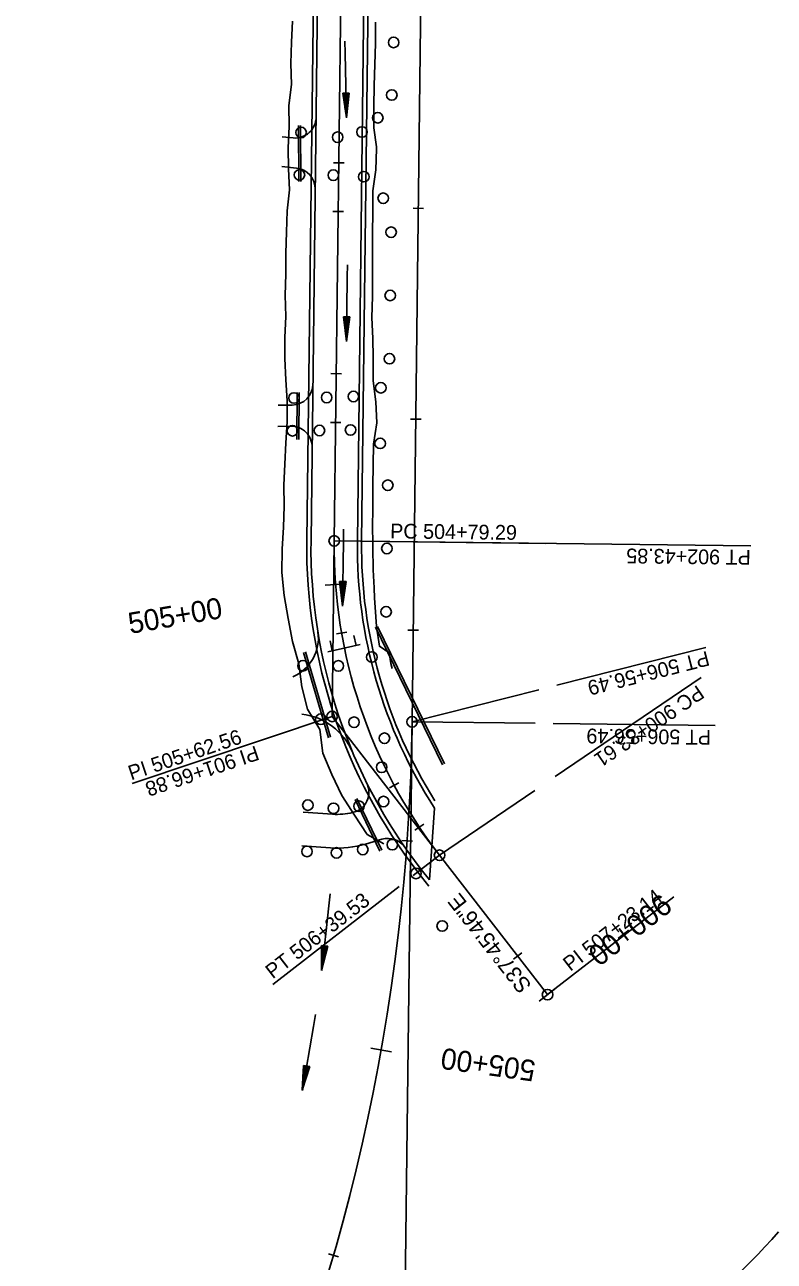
# Model space of a CAD drawing. Extents: x 1300404 to 1323571, y 234004 to 252077.
# Drawn here: x 1309789 to 1310144, y 240637 to 241223 of the extents above; entities that cross this region are included whole.
import ezdxf

# ---------------------------------------------------------------- set-up
doc = ezdxf.new("R2010")
doc.units = 0
for name, color, linetype in [('R_Barrel', 7, 'Continuous'), ('R_Const Limits', 7, 'Continuous'), ('R_Detour', 7, 'Continuous'), ('R_Flow Arrows', 7, 'Continuous'), ('R_Horz Alg Annot', 7, 'Continuous'), ('R_Horz Alg Annot Leader', 7, 'Continuous'), ('R_Horz Alg Major Ticks', 7, 'Continuous'), ('R_Horz Alg Minor Ticks', 7, 'Continuous'), ('R_Horz Alg Station Annot', 7, 'Continuous'), ('R_Horz Alg Tangents', 7, 'Continuous'), ('R_Lane Edge', 7, 'Continuous'), ('R_MOT Proposed', 7, 'Continuous'), ('R_No Plot', 7, 'Continuous'), ('R_Proposed', 7, 'Continuous'), ('R_Shoulder', 7, 'Continuous'), ('R_Temp Drainage', 7, 'Continuous')]:
    doc.layers.add(name, color=color, linetype=linetype)

msp = doc.modelspace()

# ---------------------------------------------------------------- linework, layer by layer
at = {"layer": 'R_Barrel'}
for p, q in [((1309945.82, 240929.07), (1309944.77, 240933.75)), ((1309947.77, 240929.51), (1309932.32, 240926.06)), ((1309934.43, 240926.53), (1309933.39, 240931.2))]:
    msp.add_line(p, q, dxfattribs=at)
for centre in [(1309963.56, 241215.04), (1309962.67, 241190.12), (1309956.03, 241179.33), (1309919.68, 241172.34), (1309937, 241170.1), (1309948.56, 241172.58), (1309918.9, 241152.22), (1309934.97, 241152.09), (1309949.43, 241151.36), (1309958.65, 241141.16), (1309962.37, 241125.05), (1309961.97, 241095.05), (1309961.57, 241065.05), (1309944.5, 241047.14), (1309957.49, 241051.27), (1309916.32, 241046.44), (1309931.8, 241046.67), (1309915.58, 241030.89), (1309928.37, 241031.02), (1309943.16, 241031.28), (1309957.19, 241024.9), (1309960.78, 241005.06), (1309960.38, 240975.06), (1309959.99, 240945.06), (1309920.57, 240919.45), (1309937.35, 240919.38), (1309953.23, 240923.58), (1309929.03, 240894.12), (1309944.8, 240892.66), (1309959.19, 240885.07), (1309957.9, 240871.31), (1309922.89, 240853.37), (1309958.79, 240855.07), (1309935.04, 240851.85), (1309947.15, 240852.84), (1309922.48, 240831.42), (1309936.48, 240830.72), (1309948.95, 240832.32), (1309962.94, 240834.63), (1309974.17, 240820.96), (1309986.63, 240796.05)]:
    msp.add_circle(centre, 2.5, dxfattribs=at)
at = {"layer": 'R_Const Limits'}
for points in [[(1310136.46, 240640.42), (1310136.46, 240640.42), (1310139.66, 240643.87), (1310142.9, 240647.43), (1310146.08, 240651.04)], [(1310032.23, 240538.98), (1310032.23, 240538.98), (1310035.64, 240545.7), (1310042.03, 240553.59), (1310050.31, 240559.31), (1310056.72, 240567.17), (1310065.03, 240572.86), (1310072.78, 240579.19), (1310079.99, 240586.13), (1310086.85, 240593.48), (1310094.35, 240600.09), (1310101.6, 240607), (1310105.16, 240610.41), (1310108.95, 240613.79), (1310116.27, 240620.61), (1310123.42, 240627.63), (1310130.62, 240634.58), (1310136.46, 240640.42), (1310136.46, 240640.42)]]:
    msp.add_lwpolyline(points, dxfattribs=at)
at = {"layer": 'R_Detour'}
for p, q in [((1309922.38, 240978.84), (1309927.56, 241405.81)), ((1309924.38, 240978.82), (1309929.56, 241405.78)), ((1309946.38, 240978.55), (1309951.56, 241405.52)), ((1309948.38, 240978.53), (1309953.56, 241405.49)), ((1309915.84, 241169.75), (1309910.73, 241170.31)), ((1309917.49, 241155.49), (1309910.51, 241156.25)), ((1309915.46, 241043.1), (1309908.75, 241042.98)), ((1309914.74, 241033.08), (1309908.59, 241032.97)), ((1309934.64, 240849.05), (1309920.61, 240850)), ((1309980.53, 240817.87), (1309982.98, 240851.94)), ((1309933.56, 240833.08), (1309920.05, 240834)), ((1309950.24, 240834.89), (1309958.02, 240837.16)), ((1309980.26, 240814.95), (1309975.09, 240821.63)), ((1309980.53, 240817.87), (1309976.67, 240822.86))]:
    msp.add_line(p, q, dxfattribs=at)
for points in [[(1309958.89, 240834.93), (1309951, 240839.45), (1309944.98, 240848.63), (1309939.05, 240857.93), (1309934.23, 240867.84), (1309929.96, 240877.99), (1309928.53, 240889.17), (1309922.74, 240898.8), (1309920, 240909.46), (1309918.64, 240920.42), (1309915.59, 240931), (1309913.57, 240941.82), (1309911.7, 240952.7), (1309910.51, 240963.68), (1309910.72, 240974.73), (1309911.35, 240985.12), (1309911.68, 240995.12), (1309911.51, 241005.12), (1309912.03, 241015.12), (1309912.41, 241025.11), (1309913.07, 241035.11), (1309913.01, 241045.11), (1309912.38, 241055.12), (1309911.91, 241065.12), (1309911.98, 241075.12), (1309912.46, 241085.12), (1309912.09, 241095.12), (1309912.47, 241105.12), (1309912.5, 241115.12), (1309912.76, 241125.12), (1309913.14, 241135.11), (1309914.15, 241145.1), (1309913.68, 241155.11), (1309913.6, 241165.11), (1309914, 241175.11), (1309913.92, 241185.11), (1309915.17, 241195.09), (1309914.84, 241205.1), (1309915.11, 241215.09), (1309915.6, 241225.09)], [(1309955.03, 241224.61), (1309954.92, 241214.61), (1309954.66, 241204.61), (1309954.34, 241194.62), (1309954.17, 241184.62), (1309954.24, 241174.62), (1309955.4, 241165.57), (1309955.37, 241164.6), (1309955.09, 241154.61), (1309953.7, 241144.62), (1309953.65, 241134.62), (1309953.61, 241124.62), (1309953.6, 241114.62), (1309953.56, 241104.62), (1309953.51, 241094.62), (1309953.3, 241084.62), (1309953.69, 241074.62), (1309953.91, 241065.58), (1309953.92, 241064.61), (1309953.94, 241054.61), (1309955.14, 241044.6), (1309955.61, 241034.59), (1309953.99, 241024.61), (1309953.89, 241014.61), (1309953.69, 241004.61), (1309953.73, 240994.61), (1309953.61, 240984.61), (1309953.64, 240978.46), (1309953.64, 240974.9), (1309953.82, 240965.67), (1309953.85, 240965.01), (1309954.27, 240956.44), (1309954.5, 240951.56), (1309954.74, 240947.18), (1309955.4, 240938.04), (1309955.41, 240937.9), (1309956.84, 240928.7), (1309961.5, 240925.57), (1309962.27, 240920.49), (1309962.95, 240918.11)]]:
    msp.add_lwpolyline(points, dxfattribs=at)
for centre, radius, start, end in [((1309916.82, 241179.7), 10, 264.42549, 359.30499), ((1309916.4, 241145.55), 10, 359.30499, 83.77841), ((1309915.28, 241053.1), 10, 271.024, 359.30499), ((1309914.92, 241023.09), 10, 359.30499, 91.024), ((1310174.09, 240975.79), 251.73, 179.30499, 217.76287), ((1310174.09, 240975.79), 249.73, 179.30499, 217.76287), ((1310174.09, 240975.79), 227.73, 179.30499, 212.9461), ((1310174.09, 240975.79), 225.73, 179.30499, 212.24027), ((1309907.88, 240932.59), 20, 293.26209, 8.25693), ((1309916.5, 240866.72), 30, 22.94808, 83.23633), ((1309941.82, 240859.55), 10, 283.16838, 26.58532), ((1309936.81, 240880.97), 32, 266.11347, 283.16838), ((1309936.81, 240880.97), 48, 266.11347, 286.24882), ((1309960.82, 240827.56), 10, 34.80032, 106.24882)]:
    msp.add_arc(centre, radius, start, end, dxfattribs=at)
at = {"layer": 'R_Flow Arrows'}
for p, q in [((1309942.46, 241191), (1309939.42, 241190.95)), ((1309939.42, 241190.95), (1309941.15, 241179.23)), ((1309942.46, 241191), (1309941.15, 241179.23)), ((1309939.82, 241084.92), (1309941.2, 241073.15)), ((1309942.86, 241084.88), (1309939.82, 241084.92)), ((1309942.86, 241084.88), (1309941.2, 241073.15)), ((1309937.96, 240959.45), (1309939.34, 240947.69)), ((1309941.01, 240959.42), (1309937.96, 240959.45)), ((1309941.01, 240959.42), (1309939.34, 240947.69)), ((1309929.28, 240786.84), (1309929.41, 240775)), ((1309932.3, 240786.49), (1309929.28, 240786.84)), ((1309932.3, 240786.49), (1309929.41, 240775)), ((1309920.81, 240729.96), (1309920.19, 240718.13)), ((1309923.8, 240729.42), (1309920.19, 240718.13)), ((1309923.8, 240729.42), (1309920.81, 240729.96))]:
    msp.add_line(p, q, dxfattribs=at)
for points in [[(1309940.48, 241215.71), (1309940.6, 241209.95), (1309941.15, 241179.23)], [(1309939.72, 241190.95), (1309939.76, 241188.6)], [(1309940.03, 241190.96), (1309940.11, 241186.26)], [(1309940.33, 241190.96), (1309940.44, 241184.75), (1309940.45, 241183.92)], [(1309941.55, 241190.99), (1309941.66, 241184.77), (1309941.67, 241183.93)], [(1309941.85, 241190.99), (1309941.93, 241186.29)], [(1309942.16, 241191), (1309942.2, 241188.65)], [(1309941.63, 241109.64), (1309941.57, 241103.87), (1309941.2, 241073.15)], [(1309940.13, 241084.91), (1309940.1, 241082.56)], [(1309940.43, 241084.91), (1309940.37, 241080.21)], [(1309940.74, 241084.91), (1309940.66, 241078.69), (1309940.65, 241077.86)], [(1309941.04, 241084.9), (1309940.96, 241078.69), (1309940.92, 241075.5)], [(1309941.65, 241084.89), (1309941.57, 241078.68), (1309941.52, 241075.5)], [(1309941.95, 241084.89), (1309941.88, 241078.67), (1309941.86, 241077.84)], [(1309942.26, 241084.89), (1309942.2, 241080.19)], [(1309942.56, 241084.88), (1309942.53, 241082.53)], [(1309939.77, 240984.18), (1309939.72, 240978.41), (1309939.34, 240947.69)], [(1309938.27, 240959.45), (1309938.24, 240957.1)], [(1309938.57, 240959.45), (1309938.52, 240954.75)], [(1309938.88, 240959.44), (1309938.8, 240953.23), (1309938.79, 240952.4)], [(1309939.18, 240959.44), (1309939.11, 240953.22), (1309939.06, 240950.04)], [(1309939.79, 240959.43), (1309939.71, 240953.21), (1309939.67, 240950.03)], [(1309940.09, 240959.43), (1309940.02, 240953.21), (1309940.01, 240952.38)], [(1309940.4, 240959.42), (1309940.34, 240954.72)], [(1309940.7, 240959.42), (1309940.67, 240957.07)], [(1309933.47, 240811.26), (1309932.87, 240805.53), (1309929.56, 240774.98)], [(1309929.58, 240786.81), (1309929.31, 240784.48)], [(1309929.89, 240786.77), (1309929.33, 240782.11)], [(1309930.19, 240786.74), (1309929.45, 240780.56), (1309929.35, 240779.74)], [(1309930.49, 240786.7), (1309929.76, 240780.53), (1309929.37, 240777.37)], [(1309931.09, 240786.63), (1309930.36, 240780.45), (1309929.98, 240777.3)], [(1309931.4, 240786.59), (1309930.66, 240780.42), (1309930.56, 240779.59)], [(1309931.7, 240786.56), (1309931.14, 240781.89)], [(1309932, 240786.52), (1309931.72, 240784.19)], [(1309926.52, 240754.07), (1309925.56, 240748.39), (1309920.34, 240718.11)], [(1309922.01, 240729.74), (1309920.89, 240723.63), (1309920.3, 240720.5)], [(1309921.71, 240729.8), (1309920.59, 240723.68), (1309920.43, 240722.87)], [(1309921.41, 240729.85), (1309920.56, 240725.23)], [(1309921.11, 240729.91), (1309920.68, 240727.6)], [(1309922.6, 240729.64), (1309921.48, 240723.52), (1309920.9, 240720.39)], [(1309922.9, 240729.58), (1309921.78, 240723.46), (1309921.63, 240722.64)], [(1309923.2, 240729.53), (1309922.36, 240724.9)], [(1309923.5, 240729.47), (1309923.08, 240727.16)]]:
    msp.add_lwpolyline(points, dxfattribs=at)
at = {"layer": 'R_Horz Alg Annot Leader'}
for points in [[(1309935.38, 240978.68), (1310133.05, 240976.29)], [(1310111.73, 240928.14), (1310040.93, 240910.22)], [(1310040.16, 240866.86), (1310109.4, 240913.96)], [(1310032.48, 240908.08), (1309972.34, 240892.86)], [(1309934.37, 240895.42), (1309839.56, 240863.63)], [(1309985.36, 240829.59), (1310030.57, 240860.34)]]:
    msp.add_lwpolyline(points, dxfattribs=at)
at = {"layer": 'R_Horz Alg Major Ticks'}
for points in [[(1310032.61, 240760.43), (1310040.52, 240766.55)], [(1309952.74, 240738.12), (1309962.58, 240736.37)], [(1309952.74, 240738.12), (1309962.58, 240736.37)]]:
    msp.add_lwpolyline(points, dxfattribs=at)
at = {"layer": 'R_Horz Alg Minor Ticks'}
for points in [[(1309934.77, 241134.85), (1309939.77, 241134.79)], [(1309972.8, 241136.39), (1309977.79, 241136.33)], [(1309972.8, 241136.39), (1309977.79, 241136.33)], [(1309933.56, 241034.86), (1309938.56, 241034.8)], [(1309971.58, 241036.4), (1309976.58, 241036.33)], [(1309971.58, 241036.4), (1309976.58, 241036.33)], [(1309936.4, 240934.61), (1309941.33, 240935.46)], [(1309970.37, 240936.4), (1309975.37, 240936.34)], [(1309970.37, 240936.4), (1309975.37, 240936.34)], [(1309973.7, 240841.49), (1309977.86, 240844.27)], [(1309967.49, 240836.61), (1309972.48, 240836.25)], [(1309967.49, 240836.61), (1309972.48, 240836.25)], [(1309932.63, 240640.57), (1309937.43, 240639.19)], [(1309932.63, 240640.57), (1309937.43, 240639.19)]]:
    msp.add_lwpolyline(points, dxfattribs=at)
at = {"layer": 'R_Horz Alg Tangents'}
for p, q in [((1309934.37, 240895.42), (1309935.38, 240978.68)), ((1309985.36, 240829.59), (1309934.37, 240895.42)), ((1309967.16, 240465.49), (1309972.34, 240892.86)), ((1309967.16, 240465.49), (1309972.34, 240892.86))]:
    msp.add_line(p, q, dxfattribs=at)
at = {"layer": 'R_Lane Edge'}
msp.add_arc((1309050.08, 241631.07), 1520.39, 311.16667, 327.80537, dxfattribs=at)
at = {"layer": 'R_MOT Proposed'}
for p, q in [((1309940.52, 241402.27), (1309935.38, 240978.68)), ((1309935.38, 240978.68), (1309934.37, 240895.42)), ((1309934.37, 240895.42), (1309985.36, 240829.59)), ((1309985.36, 240829.59), (1310036.57, 240763.49))]:
    msp.add_line(p, q, dxfattribs=at)
for points in [[(1309940.05, 241157.93), (1309935.05, 241157.99)], [(1309938.84, 241057.94), (1309933.84, 241058)], [(1309935.38, 240978.68), (1310035.37, 240977.47)], [(1309941.01, 240958.37), (1309931.04, 240957.62)], [(1309934.37, 240895.42), (1309839.56, 240863.63)], [(1310030.75, 240892.15), (1309972.34, 240892.86)], [(1310116.11, 240891.11), (1310039.23, 240892.05)], [(1309966.05, 240863.88), (1309961.65, 240861.52)], [(1309972.89, 240819.93), (1309985.36, 240829.59)], [(1309906.31, 240768.35), (1309966.23, 240814.77)], [(1310036.57, 240763.49), (1310096.49, 240809.91)], [(1310024.37, 240783.32), (1310020.42, 240780.26)], [(1310040.52, 240766.55), (1310032.61, 240760.43)]]:
    msp.add_lwpolyline(points, dxfattribs=at)
for centre in [(1309935.38, 240978.68), (1309934.37, 240895.42), (1309985.36, 240829.59), (1310036.57, 240763.49)]:
    msp.add_circle(centre, 2.5, dxfattribs=at)
msp.add_arc((1310174.09, 240975.79), 238.73, 179.30499, 217.76287, dxfattribs=at)
at = {"layer": 'R_Proposed'}
for p, q in [((1309935.38, 240978.68), (1309940.56, 241405.65)), ((1309972.34, 240892.86), (1309977.52, 241319.61)), ((1309972.34, 240892.86), (1309977.52, 241319.61)), ((1309972.34, 240892.86), (1309977.52, 241319.61)), ((1309972.34, 240892.86), (1309977.52, 241319.61)), ((1309972.34, 240892.86), (1309977.18, 241291.63)), ((1309972.34, 240892.86), (1309977.18, 241291.63)), ((1309972.34, 240892.86), (1309977.18, 241291.63)), ((1309972.34, 240892.86), (1309977.18, 241291.63)), ((1309972.34, 240892.86), (1309977.18, 241291.63)), ((1309972.34, 240892.86), (1309977.18, 241291.63)), ((1310036.57, 240763.49), (1309985.36, 240829.59))]:
    msp.add_line(p, q, dxfattribs=at)
for centre in [(1309935.38, 240978.68), (1309934.37, 240895.42), (1309972.34, 240892.86), (1309972.34, 240892.86), (1309985.36, 240829.59), (1310036.57, 240763.49)]:
    msp.add_circle(centre, 2.5, dxfattribs=at)
for centre, radius, start, end in [((1310174.09, 240975.79), 238.73, 179.30499, 217.76287), ((1309017.48, 240904.44), 954.93, 311.08081, 359.30499), ((1309017.48, 240904.44), 954.93, 311.08081, 359.30499), ((1309050.08, 241631.07), 1527.89, 311.16667, 327.80537), ((1309050.08, 241631.07), 1527.89, 311.16667, 327.80537), ((1309050.08, 241631.07), 1527.89, 311.16667, 327.80537), ((1309050.08, 241631.07), 1527.89, 311.16667, 327.80537)]:
    msp.add_arc(centre, radius, start, end, dxfattribs=at)
at = {"layer": 'R_Shoulder'}
msp.add_arc((1309050.08, 241631.07), 1514.39, 311.16667, 327.80537, dxfattribs=at)
at = {"layer": 'R_Temp Drainage'}
for p, q in [((1309918.61, 241149.11), (1309918.47, 241175.72)), ((1309919.61, 241149.11), (1309919.47, 241175.72)), ((1309917.61, 241026.82), (1309917.74, 241049)), ((1309918.61, 241026.81), (1309918.74, 241049)), ((1309955.86, 240938.12), (1309987.66, 240872.88)), ((1309955.86, 240938.12), (1309987.66, 240872.88)), ((1309954.96, 240937.68), (1309986.77, 240872.44)), ((1309954.96, 240937.68), (1309986.77, 240872.44)), ((1309932.64, 240885.35), (1309920.8, 240925.77)), ((1309933.6, 240885.63), (1309921.76, 240926.05)), ((1309957.09, 240831.59), (1309945.28, 240856.1)), ((1309957.99, 240832.03), (1309946.18, 240856.53))]:
    msp.add_line(p, q, dxfattribs=at)

# ---------------------------------------------------------------- texts
at = {"layer": 'R_Horz Alg Annot'}
for s, rotation, p in [('PT 902+43.85', 179.30499, (1310133.03, 240974.33)), ('PT 506+56.49', 194.20376, (1310112.27, 240926.56)), ('PC 900+83.61', 214.22331, (1310107.69, 240910.58)), ('PI 901+66.88', 198.53393, (1309898.2, 240881.71))]:
    msp.add_text(s, height=7, rotation=rotation, dxfattribs=at).set_placement(p)
at = {"layer": 'R_Horz Alg Station Annot'}
for s, rotation, p in [('900+00', 217.76287, (1310090.43, 240811.91)), ('505+00', 172.09539, (1310031.36, 240732.14))]:
    msp.add_text(s, height=10, rotation=rotation, dxfattribs=at).set_placement(p)
at = {"layer": 'R_MOT Proposed'}
for s, height, rotation, p in [('PC 504+79.29', 7, 359.30499, (1309961.9, 240979.86)), ('505+00', 10, 9.75886, (1309838.58, 240934.53)), ('PI 505+62.56', 7, 18.53393, (1309839.08, 240865.06)), ('PT 506+56.49', 7, 179.30499, (1310114.15, 240888.96)), ('PT 506+39.53', 7, 37.76287, (1309906.21, 240770.69)), ('S37%%d45\'46"E', 7.5, 128.06477, (1310029.37, 240767.9)), ('PI 507+23.14', 7, 37.76287, (1310047.36, 240774.26))]:
    msp.add_text(s, height=height, rotation=rotation, dxfattribs=at).set_placement(p)
at = {"layer": 'R_No Plot'}
for rotation, p in [(89.30499, (1309935.43, 240978.64)), (127.76287, (1309985.43, 240829.59)), (127.76287, (1310036.63, 240763.49))]:
    msp.add_text('+', height=0.1, rotation=rotation, dxfattribs=at).set_placement(p)

doc.saveas('drawing.dxf')
